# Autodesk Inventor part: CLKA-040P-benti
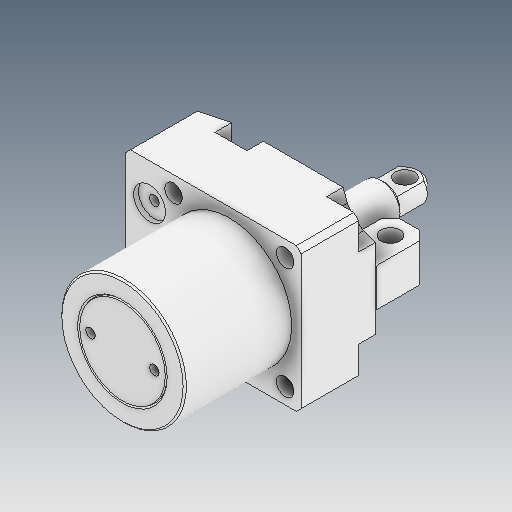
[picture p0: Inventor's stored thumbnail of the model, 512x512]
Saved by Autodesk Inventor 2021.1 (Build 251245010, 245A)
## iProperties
Created: 2021-06
Part Number: CLKA-040P-benti
Material: Ogólny
Document SubType Name: Modeling
Designer: user
Density: 1 g/cm^3
Appearance: Domyślna
Author: user
Revision Number: ÈÎºÎ
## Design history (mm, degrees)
feature "ÇÐ³ý-À­Éì14"
feature "Í¹Ì¨-À­Éì4"
node "Bryła1"
node "Bryła2"
